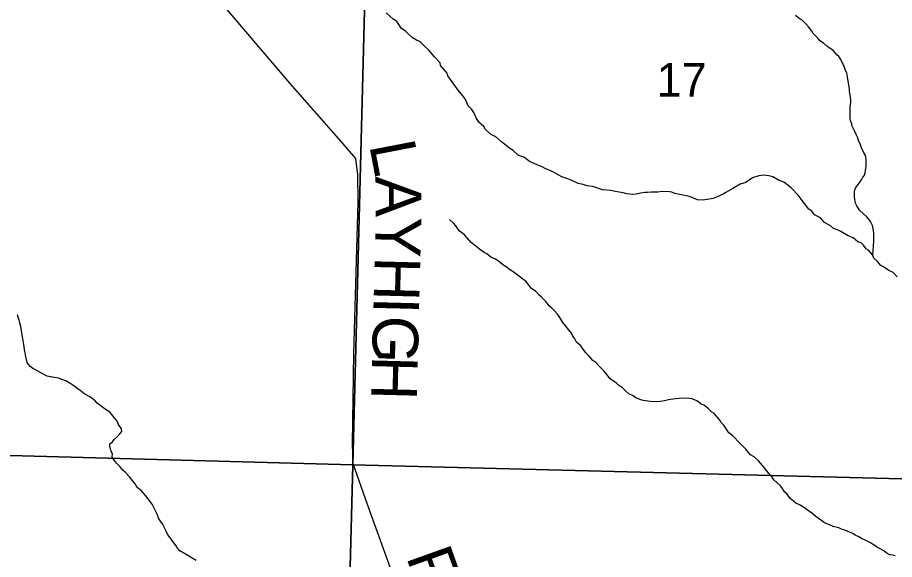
# Model space of a CAD drawing. Extents: x 0 to 34, y -2.3 to 22.
# Drawn here: x 3.123 to 4.214, y 17.278 to 17.952 of the extents above; entities that cross this region are included whole.
import ezdxf

# ---------------------------------------------------------------- set-up
doc = ezdxf.new("R2010")
doc.units = 0
for name, color, linetype in [('GM_X_County_Road', 7, 'Continuous'), ('GM_X_County_Road_Text', 7, 'Continuous'), ('GM_X_Minor_River', 7, 'Continuous'), ('GM_X_Section', 7, 'Continuous'), ('GM_X_Section_Text', 7, 'Continuous')]:
    doc.layers.add(name, color=color, linetype=linetype)

msp = doc.modelspace()

# ---------------------------------------------------------------- linework, layer by layer
at = {"layer": 'GM_X_County_Road'}
for p, q in [((3.3436, 18.0092), (3.4623, 17.8699)), ((3.4623, 17.8699), (3.5257, 17.7976)), ((3.5257, 17.7976), (3.5439, 17.7764)), ((3.5439, 17.7764), (3.5464, 17.7561)), ((3.5464, 17.7561), (3.5468, 17.7221)), ((3.5468, 17.7221), (3.5412, 17.5341)), ((3.5412, 17.5341), (3.5397, 17.4217)), ((3.5397, 17.4217), (3.5407, 17.3972)), ((3.5407, 17.3972), (3.5583, 17.3466)), ((3.5583, 17.3466), (3.6178, 17.1825))]:
    msp.add_line(p, q, dxfattribs=at)
at = {"layer": 'GM_X_Minor_River'}
for p, q in [((3.5906, 17.9501), (3.5821, 17.958)), ((3.5951, 17.947), (3.5906, 17.9501)), ((4.0958, 17.9507), (4.0914, 17.9546)), ((4.0995, 17.9487), (4.0958, 17.9507)), ((4.1043, 17.944), (4.0995, 17.9487)), ((3.6009, 17.9384), (3.5951, 17.947)), ((3.6065, 17.9345), (3.6009, 17.9384)), ((4.1073, 17.9404), (4.1043, 17.944)), ((4.1117, 17.935), (4.1073, 17.9404)), ((3.6091, 17.9321), (3.6065, 17.9345)), ((3.6142, 17.927), (3.6091, 17.9321)), ((3.6198, 17.9238), (3.6142, 17.927)), ((4.1131, 17.9319), (4.1117, 17.935)), ((4.1194, 17.926), (4.1131, 17.9319)), ((4.1212, 17.9233), (4.1194, 17.926)), ((3.6225, 17.9226), (3.6198, 17.9238)), ((3.6251, 17.921), (3.6225, 17.9226)), ((3.6291, 17.9167), (3.6251, 17.921)), ((3.6351, 17.9112), (3.6291, 17.9167)), ((4.1264, 17.9197), (4.1212, 17.9233)), ((4.1301, 17.9162), (4.1264, 17.9197)), ((4.1328, 17.9146), (4.1301, 17.9162)), ((3.642, 17.903), (3.6351, 17.9112)), ((4.138, 17.911), (4.1328, 17.9146)), ((4.1428, 17.9056), (4.138, 17.911)), ((4.1454, 17.9036), (4.1428, 17.9056)), ((3.6491, 17.8956), (3.642, 17.903)), ((3.6497, 17.8922), (3.6491, 17.8956)), ((4.1468, 17.9009), (4.1454, 17.9036)), ((4.15, 17.8947), (4.1468, 17.9009)), ((4.1518, 17.8909), (4.15, 17.8947)), ((3.6578, 17.8828), (3.6497, 17.8922)), ((3.6588, 17.8794), (3.6578, 17.8828)), ((4.1536, 17.8859), (4.1518, 17.8909)), ((4.155, 17.8832), (4.1536, 17.8859)), ((4.156, 17.8782), (4.155, 17.8832)), ((3.6661, 17.8689), (3.6588, 17.8794)), ((4.1573, 17.8702), (4.156, 17.8782)), ((3.6716, 17.8615), (3.6661, 17.8689)), ((3.6775, 17.8545), (3.6716, 17.8615)), ((4.1586, 17.8633), (4.1573, 17.8702)), ((4.1585, 17.8603), (4.1586, 17.8633)), ((3.6801, 17.851), (3.6775, 17.8545)), ((3.684, 17.8422), (3.6801, 17.851)), ((4.1598, 17.8523), (4.1585, 17.8603)), ((4.1601, 17.8496), (4.1598, 17.8523)), ((4.16, 17.8466), (4.1601, 17.8496)), ((3.6884, 17.8375), (3.684, 17.8422)), ((4.1593, 17.8337), (4.1595, 17.8413)), ((4.1595, 17.8413), (4.16, 17.8466)), ((3.691, 17.834), (3.6884, 17.8375)), ((3.6938, 17.827), (3.691, 17.834)), ((4.1595, 17.8265), (4.1593, 17.8337)), ((3.6975, 17.8216), (3.6938, 17.827)), ((3.7038, 17.8161), (3.6975, 17.8216)), ((4.1598, 17.8238), (4.1595, 17.8265)), ((4.1612, 17.8196), (4.1598, 17.8238)), ((4.1618, 17.8169), (4.1612, 17.8196)), ((4.1651, 17.81), (4.1618, 17.8169)), ((3.7048, 17.8134), (3.7038, 17.8161)), ((3.7118, 17.8068), (3.7048, 17.8134)), ((3.7186, 17.8035), (3.7118, 17.8068)), ((4.1672, 17.8057), (4.1651, 17.81)), ((3.7256, 17.7972), (3.7186, 17.8035)), ((3.7294, 17.7945), (3.7256, 17.7972)), ((4.1683, 17.803), (4.1672, 17.8057)), ((4.1697, 17.7988), (4.1683, 17.803)), ((4.1722, 17.7934), (4.1697, 17.7988)), ((3.736, 17.7889), (3.7294, 17.7945)), ((3.7401, 17.7865), (3.736, 17.7889)), ((3.7464, 17.7807), (3.7401, 17.7865)), ((4.1732, 17.79), (4.1722, 17.7934)), ((4.1768, 17.783), (4.1732, 17.79)), ((3.7543, 17.7778), (3.7464, 17.7807)), ((3.7603, 17.773), (3.7543, 17.7778)), ((4.1783, 17.7803), (4.1768, 17.783)), ((4.1793, 17.7757), (4.1783, 17.7803)), ((4.1794, 17.767), (4.1793, 17.7757)), ((3.7697, 17.7689), (3.7603, 17.773)), ((3.776, 17.7661), (3.7697, 17.7689)), ((3.7798, 17.7641), (3.776, 17.7661)), ((3.7884, 17.7604), (3.7798, 17.7641)), ((4.1785, 17.7621), (4.1794, 17.767)), ((3.7933, 17.758), (3.7884, 17.7604)), ((3.8004, 17.7536), (3.7933, 17.758)), ((3.8079, 17.7511), (3.8004, 17.7536)), ((4.0379, 17.7526), (4.0294, 17.7468)), ((4.0456, 17.755), (4.0379, 17.7526)), ((4.0513, 17.756), (4.0456, 17.755)), ((4.0582, 17.755), (4.0513, 17.756)), ((4.0631, 17.7537), (4.0582, 17.755)), ((4.0709, 17.7493), (4.0631, 17.7537)), ((4.1736, 17.7501), (4.1748, 17.7527)), ((4.1748, 17.7527), (4.1772, 17.7557)), ((4.1772, 17.7557), (4.178, 17.7587)), ((4.178, 17.7587), (4.1785, 17.7621)), ((3.8121, 17.7498), (3.8079, 17.7511)), ((3.8207, 17.7454), (3.8121, 17.7498)), ((3.8271, 17.7441), (3.8207, 17.7454)), ((3.832, 17.7424), (3.8271, 17.7441)), ((3.8388, 17.7418), (3.832, 17.7424)), ((3.843, 17.7406), (3.8388, 17.7418)), ((3.8512, 17.7376), (3.843, 17.7406)), ((4.0225, 17.7447), (4.0132, 17.7393)), ((4.0294, 17.7468), (4.0225, 17.7447)), ((4.0766, 17.7473), (4.0709, 17.7493)), ((4.0821, 17.7429), (4.0766, 17.7473)), ((4.0859, 17.7401), (4.0821, 17.7429)), ((4.1652, 17.7378), (4.1664, 17.7404)), ((4.1664, 17.7404), (4.1692, 17.7441)), ((4.1692, 17.7441), (4.1736, 17.7501)), ((3.8615, 17.7366), (3.8512, 17.7376)), ((3.8668, 17.7357), (3.8615, 17.7366)), ((3.877, 17.7338), (3.8668, 17.7357)), ((3.8815, 17.7326), (3.877, 17.7338)), ((3.8891, 17.732), (3.8815, 17.7326)), ((3.8929, 17.7322), (3.8891, 17.732)), ((3.8986, 17.7336), (3.8929, 17.7322)), ((3.904, 17.7342), (3.8986, 17.7336)), ((3.907, 17.7341), (3.904, 17.7342)), ((3.9116, 17.7347), (3.907, 17.7341)), ((3.9169, 17.7349), (3.9116, 17.7347)), ((3.92, 17.7348), (3.9169, 17.7349)), ((3.9253, 17.7354), (3.92, 17.7348)), ((3.9344, 17.7352), (3.9253, 17.7354)), ((3.9374, 17.7347), (3.9344, 17.7352)), ((3.9412, 17.7331), (3.9374, 17.7347)), ((3.9495, 17.7313), (3.9412, 17.7331)), ((3.9593, 17.7295), (3.9495, 17.7313)), ((3.9642, 17.7274), (3.9593, 17.7295)), ((4.0012, 17.7324), (3.9931, 17.7285)), ((4.0047, 17.7342), (4.0012, 17.7324)), ((4.0105, 17.7378), (4.0047, 17.7342)), ((4.0132, 17.7393), (4.0105, 17.7378)), ((4.0947, 17.7308), (4.0859, 17.7401)), ((4.0969, 17.7277), (4.0947, 17.7308)), ((4.1646, 17.7294), (4.1648, 17.7351)), ((4.1649, 17.726), (4.1646, 17.7294)), ((4.1648, 17.7351), (4.1652, 17.7378)), ((3.9695, 17.725), (3.9642, 17.7274)), ((3.9756, 17.7248), (3.9695, 17.725)), ((3.9813, 17.7254), (3.9756, 17.7248)), ((3.9889, 17.7267), (3.9813, 17.7254)), ((3.9931, 17.7285), (3.9889, 17.7267)), ((4.1079, 17.7137), (4.0969, 17.7277)), ((4.1659, 17.721), (4.1649, 17.726)), ((4.1677, 17.7176), (4.1659, 17.721)), ((4.1116, 17.7109), (4.1079, 17.7137)), ((4.1149, 17.7066), (4.1116, 17.7109)), ((4.1709, 17.7122), (4.1677, 17.7176)), ((4.1758, 17.7078), (4.1709, 17.7122)), ((4.1802, 17.7039), (4.1758, 17.7078)), ((3.6657, 17.6961), (3.6609, 17.7008)), ((4.1198, 17.7042), (4.1149, 17.7066)), ((4.1224, 17.7026), (4.1198, 17.7042)), ((4.1272, 17.6971), (4.1224, 17.7026)), ((4.1347, 17.6927), (4.1272, 17.6971)), ((4.1846, 17.6981), (4.1802, 17.7039)), ((4.1871, 17.6931), (4.1846, 17.6981)), ((3.6686, 17.6929), (3.6657, 17.6961)), ((3.673, 17.6864), (3.6686, 17.6929)), ((3.6793, 17.6816), (3.673, 17.6864)), ((4.1387, 17.6896), (4.1347, 17.6927)), ((4.1444, 17.6875), (4.1387, 17.6896)), ((4.1478, 17.6859), (4.1444, 17.6875)), ((4.1567, 17.6803), (4.1478, 17.6859)), ((4.1885, 17.6869), (4.1871, 17.6931)), ((4.1887, 17.6835), (4.1885, 17.6869)), ((3.6878, 17.6719), (3.6793, 17.6816)), ((4.1631, 17.6778), (4.1567, 17.6803)), ((4.169, 17.6731), (4.1631, 17.6778)), ((4.1887, 17.6809), (4.1887, 17.6835)), ((4.1888, 17.6736), (4.1887, 17.6809)), ((3.6982, 17.664), (3.6878, 17.6719)), ((3.7038, 17.6596), (3.6982, 17.664)), ((4.1728, 17.6715), (4.169, 17.6731)), ((4.1758, 17.6687), (4.1728, 17.6715)), ((4.1791, 17.6644), (4.1758, 17.6687)), ((4.182, 17.6624), (4.1791, 17.6644)), ((4.1876, 17.6562), (4.1888, 17.6736)), ((3.7071, 17.658), (3.7038, 17.6596)), ((3.7123, 17.654), (3.7071, 17.658)), ((3.718, 17.6512), (3.7123, 17.654)), ((4.1876, 17.6562), (4.182, 17.6624)), ((4.1886, 17.6527), (4.1876, 17.6562)), ((3.7217, 17.6488), (3.718, 17.6512)), ((3.7243, 17.6468), (3.7217, 17.6488)), ((3.7273, 17.6445), (3.7243, 17.6468)), ((3.7314, 17.6417), (3.7273, 17.6445)), ((4.1927, 17.6488), (4.1886, 17.6527)), ((4.1975, 17.6434), (4.1927, 17.6488)), ((4.2008, 17.6417), (4.1975, 17.6434)), ((3.734, 17.6393), (3.7314, 17.6417)), ((3.7377, 17.6373), (3.734, 17.6393)), ((3.7425, 17.6341), (3.7377, 17.6373)), ((3.7451, 17.6318), (3.7425, 17.6341)), ((3.7522, 17.6266), (3.7451, 17.6318)), ((4.2072, 17.6374), (4.2008, 17.6417)), ((4.2128, 17.6349), (4.2072, 17.6374)), ((4.2176, 17.6295), (4.2128, 17.6349)), ((3.7556, 17.6239), (3.7522, 17.6266)), ((3.76, 17.6184), (3.7556, 17.6239)), ((3.7629, 17.6149), (3.76, 17.6184)), ((3.7681, 17.611), (3.7629, 17.6149)), ((3.7725, 17.6067), (3.7681, 17.611)), ((3.7751, 17.6039), (3.7725, 17.6067)), ((3.7807, 17.5988), (3.7751, 17.6039)), ((3.7854, 17.593), (3.7807, 17.5988)), ((3.788, 17.5906), (3.7854, 17.593)), ((3.7906, 17.5879), (3.788, 17.5906)), ((3.7954, 17.5824), (3.7906, 17.5879)), ((3.1243, 17.5792), (3.1233, 17.5819)), ((3.1254, 17.5754), (3.1243, 17.5792)), ((3.798, 17.5789), (3.7954, 17.5824)), ((3.802, 17.5727), (3.798, 17.5789)), ((3.1261, 17.5723), (3.1254, 17.5754)), ((3.1274, 17.5677), (3.1261, 17.5723)), ((3.1287, 17.5597), (3.1274, 17.5677)), ((3.8056, 17.5681), (3.802, 17.5727)), ((3.8126, 17.5591), (3.8056, 17.5681)), ((3.1294, 17.5552), (3.1287, 17.5597)), ((3.131, 17.5452), (3.1294, 17.5552)), ((3.8144, 17.5557), (3.8126, 17.5591)), ((3.8162, 17.5529), (3.8144, 17.5557)), ((3.1319, 17.5391), (3.131, 17.5452)), ((3.8187, 17.5483), (3.8162, 17.5529)), ((3.8243, 17.5436), (3.8187, 17.5483)), ((3.1339, 17.5284), (3.1319, 17.5391)), ((3.8283, 17.5378), (3.8243, 17.5436)), ((3.8305, 17.535), (3.8283, 17.5378)), ((3.8346, 17.5307), (3.8305, 17.535)), ((3.1352, 17.5227), (3.1339, 17.5284)), ((3.1385, 17.5184), (3.1352, 17.5227)), ((3.839, 17.5253), (3.8346, 17.5307)), ((3.8427, 17.5229), (3.839, 17.5253)), ((3.846, 17.519), (3.8427, 17.5229)), ((3.1423, 17.5153), (3.1385, 17.5184)), ((3.1449, 17.514), (3.1423, 17.5153)), ((3.1576, 17.5072), (3.1449, 17.514)), ((3.8527, 17.5124), (3.846, 17.519)), ((3.8552, 17.5096), (3.8527, 17.5124)), ((3.1602, 17.506), (3.1576, 17.5072)), ((3.167, 17.5047), (3.1602, 17.506)), ((3.1742, 17.5033), (3.167, 17.5047)), ((3.1772, 17.5021), (3.1742, 17.5033)), ((3.1836, 17.5), (3.1772, 17.5021)), ((3.8607, 17.5026), (3.8552, 17.5096)), ((3.8659, 17.4987), (3.8607, 17.5026)), ((3.1896, 17.4964), (3.1836, 17.5)), ((3.1922, 17.4944), (3.1896, 17.4964)), ((3.203, 17.4869), (3.1922, 17.4944)), ((3.8686, 17.4971), (3.8659, 17.4987)), ((3.8712, 17.4947), (3.8686, 17.4971)), ((3.876, 17.4911), (3.8712, 17.4947)), ((3.8801, 17.4872), (3.876, 17.4911)), ((3.2071, 17.4833), (3.203, 17.4869)), ((3.2142, 17.4797), (3.2071, 17.4833)), ((3.2198, 17.475), (3.2142, 17.4797)), ((3.8838, 17.4837), (3.8801, 17.4872)), ((3.8883, 17.4817), (3.8838, 17.4837)), ((3.8927, 17.4789), (3.8883, 17.4817)), ((3.8976, 17.4768), (3.8927, 17.4789)), ((3.9539, 17.4786), (3.9463, 17.478)), ((3.96, 17.478), (3.9539, 17.4786)), ((3.2224, 17.4722), (3.2198, 17.475)), ((3.2257, 17.4699), (3.2224, 17.4722)), ((3.2309, 17.4659), (3.2257, 17.4699)), ((3.9018, 17.4756), (3.8976, 17.4768)), ((3.9048, 17.4751), (3.9018, 17.4756)), ((3.9105, 17.4742), (3.9048, 17.4751)), ((3.9188, 17.4739), (3.9105, 17.4742)), ((3.9234, 17.4742), (3.9188, 17.4739)), ((3.9284, 17.4751), (3.9234, 17.4742)), ((3.9333, 17.4765), (3.9284, 17.4751)), ((3.9421, 17.4774), (3.9333, 17.4765)), ((3.9463, 17.478), (3.9421, 17.4774)), ((3.9626, 17.4775), (3.96, 17.478)), ((3.9687, 17.4751), (3.9626, 17.4775)), ((3.9735, 17.4715), (3.9687, 17.4751)), ((3.978, 17.4695), (3.9735, 17.4715)), ((3.9832, 17.4652), (3.978, 17.4695)), ((3.2387, 17.4604), (3.2309, 17.4659)), ((3.2472, 17.4499), (3.2387, 17.4604)), ((3.9873, 17.4612), (3.9832, 17.4652)), ((3.9902, 17.4592), (3.9873, 17.4612)), ((3.9928, 17.4561), (3.9902, 17.4592)), ((3.2489, 17.4456), (3.2472, 17.4499)), ((3.9972, 17.4511), (3.9928, 17.4561)), ((3.999, 17.4483), (3.9972, 17.4511)), ((4.002, 17.4448), (3.999, 17.4483)), ((3.2526, 17.4402), (3.2489, 17.4456)), ((3.2505, 17.4342), (3.2533, 17.4371)), ((3.2533, 17.4371), (3.2526, 17.4402)), ((4.0064, 17.4386), (4.002, 17.4448)), ((4.0082, 17.4355), (4.0064, 17.4386)), ((4.0134, 17.4316), (4.0082, 17.4355)), ((3.238, 17.4216), (3.2415, 17.4242)), ((3.2415, 17.4242), (3.2435, 17.4272)), ((3.2435, 17.4272), (3.2474, 17.4305)), ((3.2474, 17.4305), (3.2505, 17.4342)), ((4.0219, 17.4226), (4.0134, 17.4316)), ((3.2383, 17.419), (3.238, 17.4216)), ((3.24, 17.4121), (3.2383, 17.419)), ((4.027, 17.4175), (4.0219, 17.4226)), ((4.0296, 17.4151), (4.027, 17.4175)), ((4.0329, 17.4109), (4.0296, 17.4151)), ((3.2414, 17.409), (3.24, 17.4121)), ((3.2413, 17.4052), (3.2414, 17.409)), ((3.2442, 17.4009), (3.2413, 17.4052)), ((4.0351, 17.4081), (4.0329, 17.4109)), ((4.04, 17.4053), (4.0351, 17.4081)), ((4.0452, 17.4006), (4.04, 17.4053)), ((3.2464, 17.3975), (3.2442, 17.4009)), ((3.2508, 17.3935), (3.2464, 17.3975)), ((3.2549, 17.3885), (3.2508, 17.3935)), ((4.0477, 17.3975), (4.0452, 17.4006)), ((4.0525, 17.3921), (4.0477, 17.3975)), ((4.058, 17.3847), (4.0525, 17.3921)), ((3.2575, 17.3861), (3.2549, 17.3885)), ((3.2626, 17.3806), (3.2575, 17.3861)), ((3.2678, 17.3744), (3.2626, 17.3806)), ((4.0613, 17.3815), (4.058, 17.3847)), ((4.0642, 17.3769), (4.0613, 17.3815)), ((3.2696, 17.3717), (3.2678, 17.3744)), ((3.2721, 17.3674), (3.2696, 17.3717)), ((4.072, 17.3698), (4.0642, 17.3769)), ((4.0742, 17.3671), (4.072, 17.3698)), ((3.2777, 17.3631), (3.2721, 17.3674)), ((3.2825, 17.3573), (3.2777, 17.3631)), ((4.0775, 17.3617), (4.0742, 17.3671)), ((4.0808, 17.3589), (4.0775, 17.3617)), ((4.0845, 17.3535), (4.0808, 17.3589)), ((3.2854, 17.3537), (3.2825, 17.3573)), ((3.2909, 17.3467), (3.2854, 17.3537)), ((4.0886, 17.3503), (4.0845, 17.3535)), ((4.0915, 17.348), (4.0886, 17.3503)), ((4.0964, 17.3459), (4.0915, 17.348)), ((3.2956, 17.3375), (3.2909, 17.3467)), ((3.297, 17.334), (3.2956, 17.3375)), ((4.1024, 17.3419), (4.0964, 17.3459)), ((4.1057, 17.3396), (4.1024, 17.3419)), ((4.1117, 17.3352), (4.1057, 17.3396)), ((3.2991, 17.3283), (3.297, 17.334)), ((3.3039, 17.3221), (3.2991, 17.3283)), ((4.1165, 17.3313), (4.1117, 17.3352)), ((4.1213, 17.3277), (4.1165, 17.3313)), ((4.1239, 17.3257), (4.1213, 17.3277)), ((4.1273, 17.3233), (4.1239, 17.3257)), ((3.3082, 17.3128), (3.3039, 17.3221)), ((4.1307, 17.3221), (4.1273, 17.3233)), ((4.1337, 17.3209), (4.1307, 17.3221)), ((4.1382, 17.3188), (4.1337, 17.3209)), ((4.145, 17.3171), (4.1382, 17.3188)), ((4.1484, 17.3155), (4.145, 17.3171)), ((4.1525, 17.3142), (4.1484, 17.3155)), ((3.3103, 17.3086), (3.3082, 17.3128)), ((3.3206, 17.2946), (3.3103, 17.3086)), ((4.1585, 17.3118), (4.1525, 17.3142)), ((4.1626, 17.3101), (4.1585, 17.3118)), ((4.1656, 17.3081), (4.1626, 17.3101)), ((4.1701, 17.3061), (4.1656, 17.3081)), ((4.1735, 17.3037), (4.1701, 17.3061)), ((3.3224, 17.2919), (3.3206, 17.2946)), ((4.178, 17.3017), (4.1735, 17.3037)), ((4.1814, 17.3001), (4.178, 17.3017)), ((4.1844, 17.2985), (4.1814, 17.3001)), ((4.187, 17.2969), (4.1844, 17.2985)), ((4.1929, 17.2929), (4.187, 17.2969)), ((3.3253, 17.2884), (3.3224, 17.2919)), ((3.3324, 17.2844), (3.3253, 17.2884)), ((3.3407, 17.2792), (3.3324, 17.2844)), ((4.2012, 17.2885), (4.1929, 17.2929)), ((4.2053, 17.2853), (4.2012, 17.2885)), ((4.2086, 17.2837), (4.2053, 17.2853)), ((4.212, 17.2832), (4.2086, 17.2837)), ((4.2154, 17.2823), (4.212, 17.2832)), ((3.3455, 17.2764), (3.3407, 17.2792))]:
    msp.add_line(p, q, dxfattribs=at)
at = {"layer": 'GM_X_Section'}
for p, q in [((3.5658, 18.3983), (3.5407, 17.3953)), ((3.5407, 17.3953), (3.5658, 18.3983)), ((3.5407, 17.3953), (2.5318, 17.4232)), ((2.5318, 17.4232), (3.5407, 17.3953)), ((3.5407, 17.3953), (3.5141, 16.4057)), ((3.5141, 16.4057), (3.5407, 17.3953)), ((4.3385, 17.3752), (3.5407, 17.3953)), ((3.5407, 17.3953), (4.3385, 17.3752))]:
    msp.add_line(p, q, dxfattribs=at)

# ---------------------------------------------------------------- texts
at = {"layer": 'GM_X_County_Road_Text'}
for s, rotation, p in [('L', 280.9008, (3.5608, 17.7934)), ('A', 270.4526, (3.5686, 17.7544)), ('Y', 268.632, (3.569, 17.7048)), ('H', 268.5382, (3.5678, 17.6549)), ('I', 268.5381, (3.5665, 17.6049)), ('G', 268.5395, (3.5659, 17.5816)), ('H', 268.5382, (3.5647, 17.5316)), ('R', 289.6915, (3.6065, 17.2812))]:
    msp.add_text(s, height=0.0568, rotation=rotation, dxfattribs=at).set_placement(p)
at = {"layer": 'GM_X_Section_Text'}
msp.add_text('17', height=0.04186, rotation=0, dxfattribs=at).set_placement((3.9184, 17.8534))

doc.saveas('drawing.dxf')
